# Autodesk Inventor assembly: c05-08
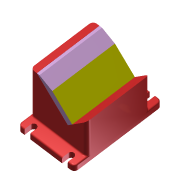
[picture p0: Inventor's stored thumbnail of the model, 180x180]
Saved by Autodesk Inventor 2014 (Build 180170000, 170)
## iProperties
Created: 2010-11
Part Number: c05-08
Document SubType Name: Assembly
Designer: Thom Tremblay
Author: Thom Tremblay
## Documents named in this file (3)
- C:\Inventor 2014 Essentials\Assemblies\Chapter 05\c05-08.iam
- C:\Inventor 2014 Essentials\Parts\Chapter 05\c05-07.ipt
- C:\Inventor 2014 Essentials\Parts\Chapter 05\c05-08.ipt
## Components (2 placed, 2 different names)
1. c05-07:1 — Mate:1, Mate:2, Flush:1
2. c05-08:1 — Mate:1, Mate:2, Flush:1
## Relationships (3: Mate 2, Flush 1)
- Mate:1: c05-07:1 ↔ c05-08:1
- Mate:2: c05-07:1 ↔ c05-08:1
- Flush:1: c05-07:1 ↔ c05-08:1
